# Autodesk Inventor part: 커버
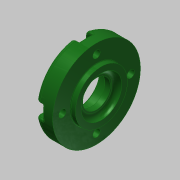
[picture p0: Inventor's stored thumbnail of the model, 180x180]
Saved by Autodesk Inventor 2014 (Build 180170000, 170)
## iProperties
Created: 2015-11
Part Number: 커버
Material: 알루미늄 6061
Document SubType Name: Modeling
Designer: mduedu
Density: 1 g/cm^3
Appearance: 매끄러움 - 짙은 산림 녹색
Author: mduedu
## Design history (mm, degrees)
sketch "스케치1"
  geometry: L1 (-7, 0)-(7, 0); L2 (-7, 0)-(-7, 27); L3 (-7, 27)-(4, 27); L4 (4, 27)-(4, 16); L5 (4, 16)-(7, 16); L6 (7, 16)-(7, 0); 2 further points
  constraints: 12 end point, 3 perpendicular, 2 parallel, 1 coincident, 1 horizontal, 1 midpoint
  dimensions: "d0" = 14 distance of L1.start L1.end; "d1" = 54 diameter of L3 L1; "d2" = 3 distance of L4.end L5.end; "d3" = 32 diameter of L5 L1
revolve "회전1" sketch "스케치1" stored, may be unused: angle "d4" = 90 deg
hole "구멍1" diameter "d7" = 25; stored, may be unused: countersink angle "d11" = 90 deg, drill point angle "d13" = 0 deg; dims "d5" = 10, "d6" = 10, "d8" = 6, "d9" = 4, "d10" = 2, "d12" = 3
hole "구멍2" diameter "d16" = 25; stored, may be unused: countersink angle "d20" = 90 deg, drill point angle "d22" = 0 deg; dims "d17" = 6, "d18" = 4, "d19" = 2, "d21" = 7.7, "d58" = 10, "d59" = 10
hole "구멍3" diameter "d25" = 17; stored, may be unused: countersink angle "d29" = 90 deg, drill point angle "d31" = 0 deg; dims "d23" = 10, "d24" = 10, "d26" = 6, "d27" = 4, "d28" = 2, "d30" = 4.2
chamfer "모따기1" distance "d32" = 0.6; stored, may be unused: second distance "d33" = 2, angle "d34" = 30 deg
fillet "모깎기1" dims "d35" = 0.3
fillet "모깎기2" dims "d36" = 3
fillet "모깎기3" dims "d37" = 3
fillet "모깎기4" dims "d38" = 0.3
sketch "스케치3" dims "d61" = 42
  geometry: C1 r 27 at (0, 0) reference; 2 further points
  constraints: 2 vertical alignment, 1 coincident, 2 other
hole "구멍4" sketch "스케치3" at (0, 21) diameter "d44" = 4.5; stored, may be unused: countersink angle "d48" = 90 deg, drill point angle "d50" = 0 deg; dims "d45" = 6, "d46" = 8, "d47" = 4.6, "d49" = 8
sketch "스케치4"
  geometry: L1 (-4, 5.702)-(-4, 0); L2 (4, 5.702)-(4, 0); A1 r 27 centre (0, -21) between (-4, 5.702) and (4, 5.702) reference; A2 r 4 centre (0, 0) between (-2.824, 2.833) and (2.824, 2.833) reference
  constraints: 4 end point, 4 point on circle, 2 tangent, 2 vertical
extrude "돌출1" cut sketch "스케치4" stored distance "d51" = 0; taper "d52" = 0 deg
fillet "모깎기5" dims "d56" = 0.3
fillet "모깎기6" dims "d57" = 1
node "솔리드1"
pattern_circular "원형 패턴2" dims angle "d64" = 360 deg
pattern_circular "원형 패턴1" dims angle "d54" = 360 deg
